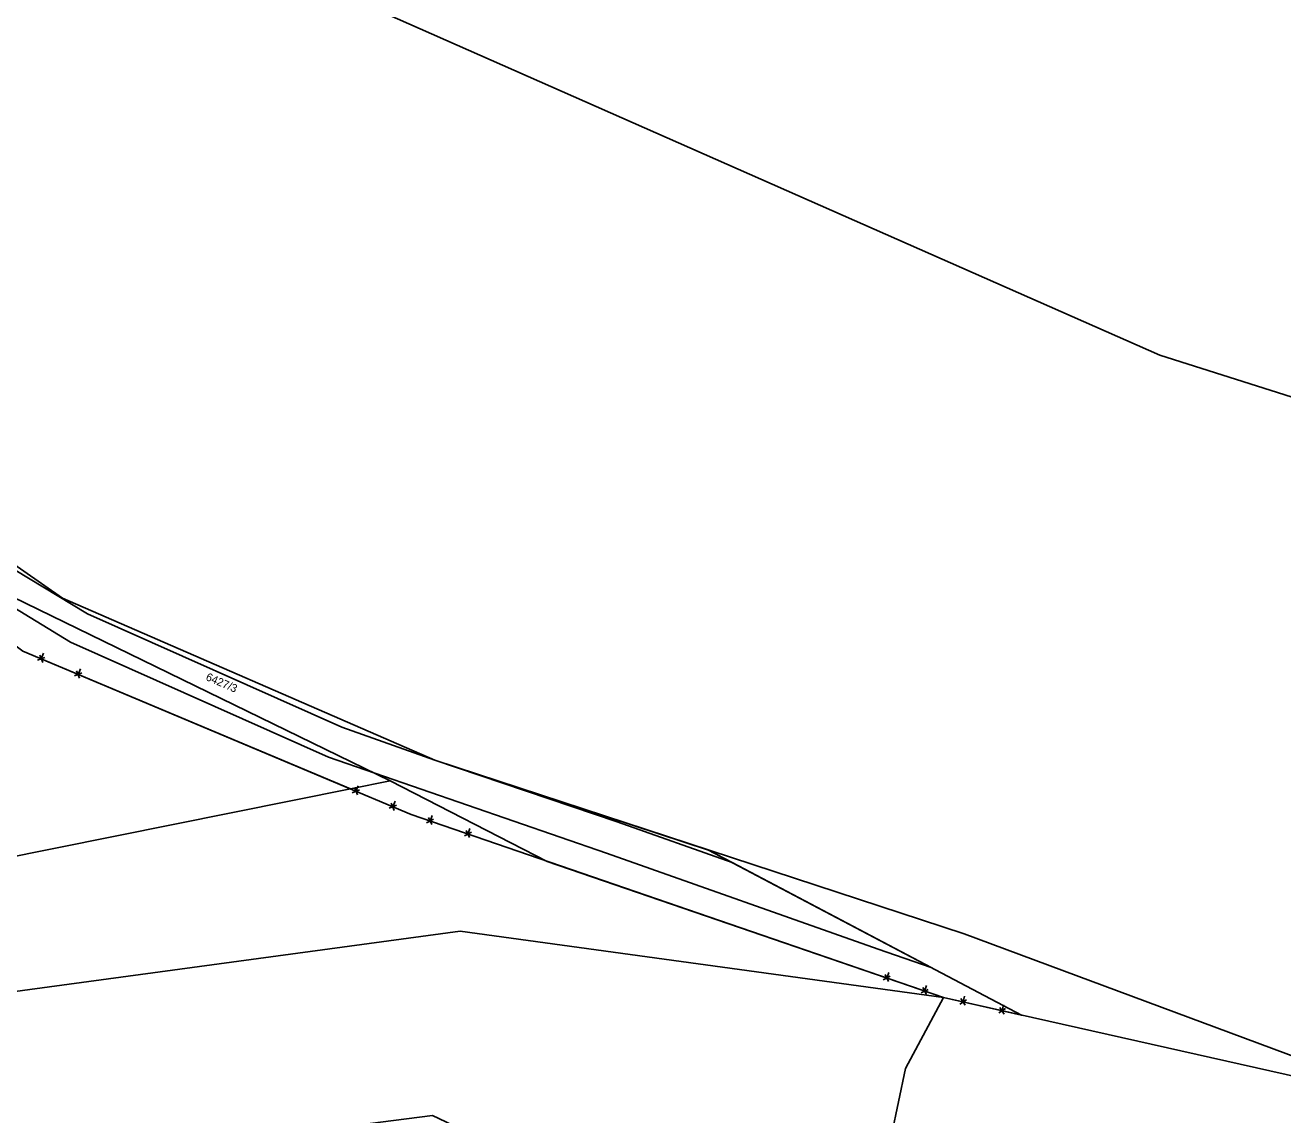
# Model space of a CAD drawing. Extents: x -439750 to -439180, y -1258684 to -1258308.
# Drawn here: x -439607.3 to -439544.4, y -1258619.8 to -1258565.3 of the extents above; entities that cross this region are included whole.
import ezdxf

# ---------------------------------------------------------------- set-up
doc = ezdxf.new("R2010")
doc.units = 0
for name, color, linetype in [('KATASTER', 7, 'Continuous'), ('TARCHY', 7, 'Continuous'), ('UOV', 7, 'Continuous')]:
    doc.layers.add(name, color=color, linetype=linetype)

# ---------------------------------------------------------------- blocks, each defined once
blk = doc.blocks.new('2072')
for p, q in [((-4.3, 0.7), (-5.7, -0.7)), ((-5.7, 0.7), (-4.3, -0.7)), ((-5, 0), (-5, -1.5)), ((4.3, 0.7), (5.7, -0.7)), ((5.7, 0.7), (4.3, -0.7)), ((5, 0), (5, -1.5))]:
    blk.add_line(p, q)

msp = doc.modelspace()

# ---------------------------------------------------------------- linework, layer by layer
at = {"layer": 'KATASTER'}
for points in [[(-439548.5, -1258497.7), (-439538.17, -1258484.88), (-439520.19, -1258486.95), (-439507.21, -1258497.49), (-439484.47, -1258496.42), (-439400.54, -1258499.28), (-439387.09, -1258499.74), (-439411.19, -1258562.66), (-439413.56, -1258566.65), (-439437.77, -1258626.82), (-439438.12, -1258627.38), (-439482.75, -1258611.76), (-439518.67, -1258591.95), (-439550.54, -1258581.84), (-439567.51, -1258574.36), (-439597.45, -1258561.13)], [(-439704.8, -1258494.65), (-439703.92, -1258521.17), (-439680.15, -1258515.08), (-439678.62, -1258514.6), (-439678.78, -1258516.82), (-439677.23, -1258536.72), (-439666.64, -1258532.76), (-439664.94, -1258530.22), (-439663.93, -1258528.71), (-439662.82, -1258519.84), (-439661.31, -1258521.55), (-439655.18, -1258528.47), (-439644.01, -1258541.08), (-439634.09, -1258562.13), (-439620.57, -1258582.24), (-439613.92, -1258591.72), (-439607.38, -1258596.63), (-439587.97, -1258604.8), (-439561.36, -1258613.95), (-439535.34, -1258619.8)], [(-439535.34, -1258619.8), (-439561.36, -1258613.95), (-439587.97, -1258604.8), (-439607.38, -1258596.63), (-439613.92, -1258591.72), (-439620.57, -1258582.24), (-439634.09, -1258562.13), (-439644.01, -1258541.08), (-439655.18, -1258528.47), (-439661.31, -1258521.55), (-439662.82, -1258519.84), (-439663.93, -1258528.71), (-439664.94, -1258530.22), (-439666.64, -1258532.76), (-439677.23, -1258536.72), (-439678.78, -1258516.82), (-439678.62, -1258514.6), (-439680.15, -1258515.08), (-439703.92, -1258521.17), (-439704.8, -1258494.65)], [(-439662.28, -1258501.2), (-439658.45, -1258512.88), (-439640.46, -1258538.63), (-439631.04, -1258560.29), (-439618.29, -1258580.27), (-439611.21, -1258589.93), (-439605.4, -1258593.99), (-439586.79, -1258602.08), (-439560.33, -1258610.77), (-439542.1, -1258617.55)], [(-439535.34, -1258619.8), (-439561.36, -1258613.95), (-439587.97, -1258604.8), (-439607.38, -1258596.63), (-439613.92, -1258591.72), (-439620.57, -1258582.24), (-439634.09, -1258562.13), (-439644.01, -1258541.08), (-439648.8, -1258533.92), (-439660.49, -1258516.44), (-439665.91, -1258502.4)], [(-439677.23, -1258536.72), (-439666.64, -1258532.76), (-439664.94, -1258530.22), (-439663.33, -1258528.7), (-439661.31, -1258521.55), (-439655.18, -1258528.47), (-439644.01, -1258541.08), (-439634.09, -1258562.13), (-439620.57, -1258582.24), (-439613.92, -1258591.72), (-439607.38, -1258596.63), (-439587.97, -1258604.8), (-439561.36, -1258613.95), (-439585.52, -1258610.63), (-439609.02, -1258613.81), (-439634.87, -1258620.76), (-439655.28, -1258632.7), (-439678.79, -1258645.12)], [(-439678.79, -1258645.12), (-439655.28, -1258632.7), (-439634.87, -1258620.76), (-439609.02, -1258613.81), (-439585.52, -1258610.63), (-439561.36, -1258613.95), (-439563.26, -1258617.5), (-439564.31, -1258622.49), (-439568.05, -1258628.83), (-439586.9, -1258619.84), (-439609.13, -1258622.7), (-439631.71, -1258628.28), (-439654.59, -1258643.31), (-439677.39, -1258653.86)]]:
    msp.add_lwpolyline(points, dxfattribs=at)
msp.add_lwpolyline([(-439640.46, -1258538.63), (-439597.45, -1258561.13), (-439567.51, -1258574.36), (-439550.54, -1258581.84), (-439518.67, -1258591.95), (-439482.75, -1258611.76), (-439438.12, -1258627.38), (-439494.8, -1258628.92), (-439535.34, -1258619.8), (-439542.1, -1258617.55), (-439560.33, -1258610.77), (-439586.79, -1258602.08), (-439605.4, -1258593.99), (-439611.21, -1258589.93), (-439618.29, -1258580.27), (-439631.04, -1258560.29)], close=True, dxfattribs=at)
at = {"layer": 'TARCHY'}
msp.add_lwpolyline([(-439644.01, -1258537.85), (-439641.56, -1258538.39), (-439640.46, -1258538.63), (-439631.04, -1258560.29), (-439618.29, -1258580.27), (-439611.21, -1258589.93), (-439605.4, -1258593.99), (-439586.79, -1258602.08), (-439573.1, -1258606.58), (-439571.93, -1258607.2), (-439561.97, -1258612.45), (-439564.63, -1258611.53), (-439578.21, -1258606.73), (-439592.11, -1258601.94), (-439605, -1258596.18), (-439612.69, -1258591.48), (-439615.6, -1258588.24), (-439616.03, -1258586.69), (-439619.73, -1258582.05), (-439628.05, -1258568.85), (-439634.58, -1258557.15), (-439641.64, -1258541.07)], close=True, dxfattribs=at)
msp.add_lwpolyline([(-439641.56, -1258538.39), (-439640.31, -1258540.09), (-439633.07, -1258556.48), (-439631.04, -1258560.29), (-439626.6, -1258568.05), (-439618.33, -1258581.17), (-439614.75, -1258585.66), (-439614.04, -1258587.7), (-439611.5, -1258590.33), (-439604.15, -1258594.77), (-439591.44, -1258600.43), (-439586.79, -1258602.08), (-439577.67, -1258605.17), (-439571.93, -1258607.2)], dxfattribs=at)
at = {"layer": 'UOV'}
for points in [[(-439677.23, -1258536.72), (-439666.64, -1258532.76), (-439664.94, -1258530.22), (-439663.33, -1258528.7), (-439661.31, -1258521.55), (-439644.01, -1258541.08), (-439634.09, -1258562.13), (-439620.57, -1258582.24), (-439613.92, -1258591.72), (-439607.38, -1258596.63), (-439591.01, -1258603.52), (-439658.86, -1258617.16), (-439684.54, -1258642.58), (-439686.09, -1258644.61), (-439698.51, -1258643.74), (-439717.85, -1258616.24), (-439718.4, -1258599.9), (-439713.55, -1258578.29), (-439704.98, -1258583.43), (-439700.34, -1258583.24), (-439692.23, -1258576.64), (-439685.44, -1258555.87), (-439684.77, -1258547.23), (-439677.24, -1258536.55)], [(-439632.35, -1258562), (-439620.95, -1258577.51), (-439611.16, -1258592.34), (-439589.02, -1258603.12), (-439591.01, -1258603.52), (-439607.38, -1258596.63), (-439613.92, -1258591.72), (-439620.57, -1258582.24), (-439634.09, -1258562.13), (-439644.01, -1258541.08), (-439648.8, -1258533.92), (-439645.84, -1258537.45)], [(-439640.46, -1258538.63), (-439631.04, -1258560.29), (-439618.29, -1258580.27), (-439611.21, -1258589.93), (-439605.4, -1258593.99), (-439586.79, -1258602.08), (-439573.1, -1258606.58), (-439557.46, -1258614.83), (-439561.36, -1258613.95), (-439581.17, -1258607.14), (-439589.02, -1258603.12), (-439611.16, -1258592.34), (-439620.95, -1258577.51), (-439632.35, -1258562), (-439645.84, -1258537.45)]]:
    msp.add_lwpolyline(points, close=True, dxfattribs=at)

# ---------------------------------------------------------------- block references
at = {"layer": 'KATASTER'}
for p, xscale, yscale, rotation in [((-439605.537, -1258597.406), 0.19999999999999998, 0.19999999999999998, 157.162323), ((-439589.813, -1258604.024), 0.19999999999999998, 0.19999999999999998, 157.162323), ((-439586.079, -1258605.45), 0.2, 0.20000000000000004, 161.00114), ((-439563.251, -1258613.3), 0.2, 0.20000000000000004, 161.00114), ((-439559.409, -1258614.389), 0.2, 0.19999999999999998, 167.303676)]:
    msp.add_blockref('2072', p, dxfattribs=dict(at, xscale=xscale, yscale=yscale, rotation=rotation))

# ---------------------------------------------------------------- texts
at = {"layer": 'UOV'}
msp.add_text('6427/3', height=0.4, rotation=336.555, dxfattribs=at).set_placement((-439598.271, -1258598.065))

doc.saveas('drawing.dxf')
